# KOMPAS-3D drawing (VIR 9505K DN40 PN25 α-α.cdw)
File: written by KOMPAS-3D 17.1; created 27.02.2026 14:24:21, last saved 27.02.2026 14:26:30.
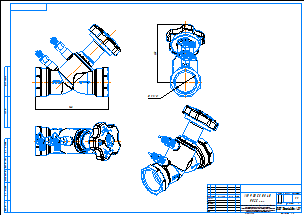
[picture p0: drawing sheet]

Sheet 1: A2, landscape

Title block, sheet 1: name: VIR 9505K DN40 / PN25 р-р; material: Внимание! Данный продукт является объектом авторского права ООО «Торговый Дом АДЛ». / Запрещается изменение, копирование, распространение / (в том числе путем копирования на другие сайты и ресурсы в Интернете) / или любое иное использование информации и объектов без предварительного / согласия правообладателя (ООО «Торговый Дом АДЛ»).; sheets: 1; organisation: ООО "Торговый дом АДЛ"; sheet format: A2

Views: Вид 1, Спереди, Проекционный вид 2, Проекционный вид 3, Вид 4, Изометрия
Referenced files in C:\Users\mipv\Desktop\VIR 9505K STP формат\: VIR 9505K DN40 PN25 р-р.m3d
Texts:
  adm
Dimensions and other numbers on the sheet: 113; 142; 1:1; 1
